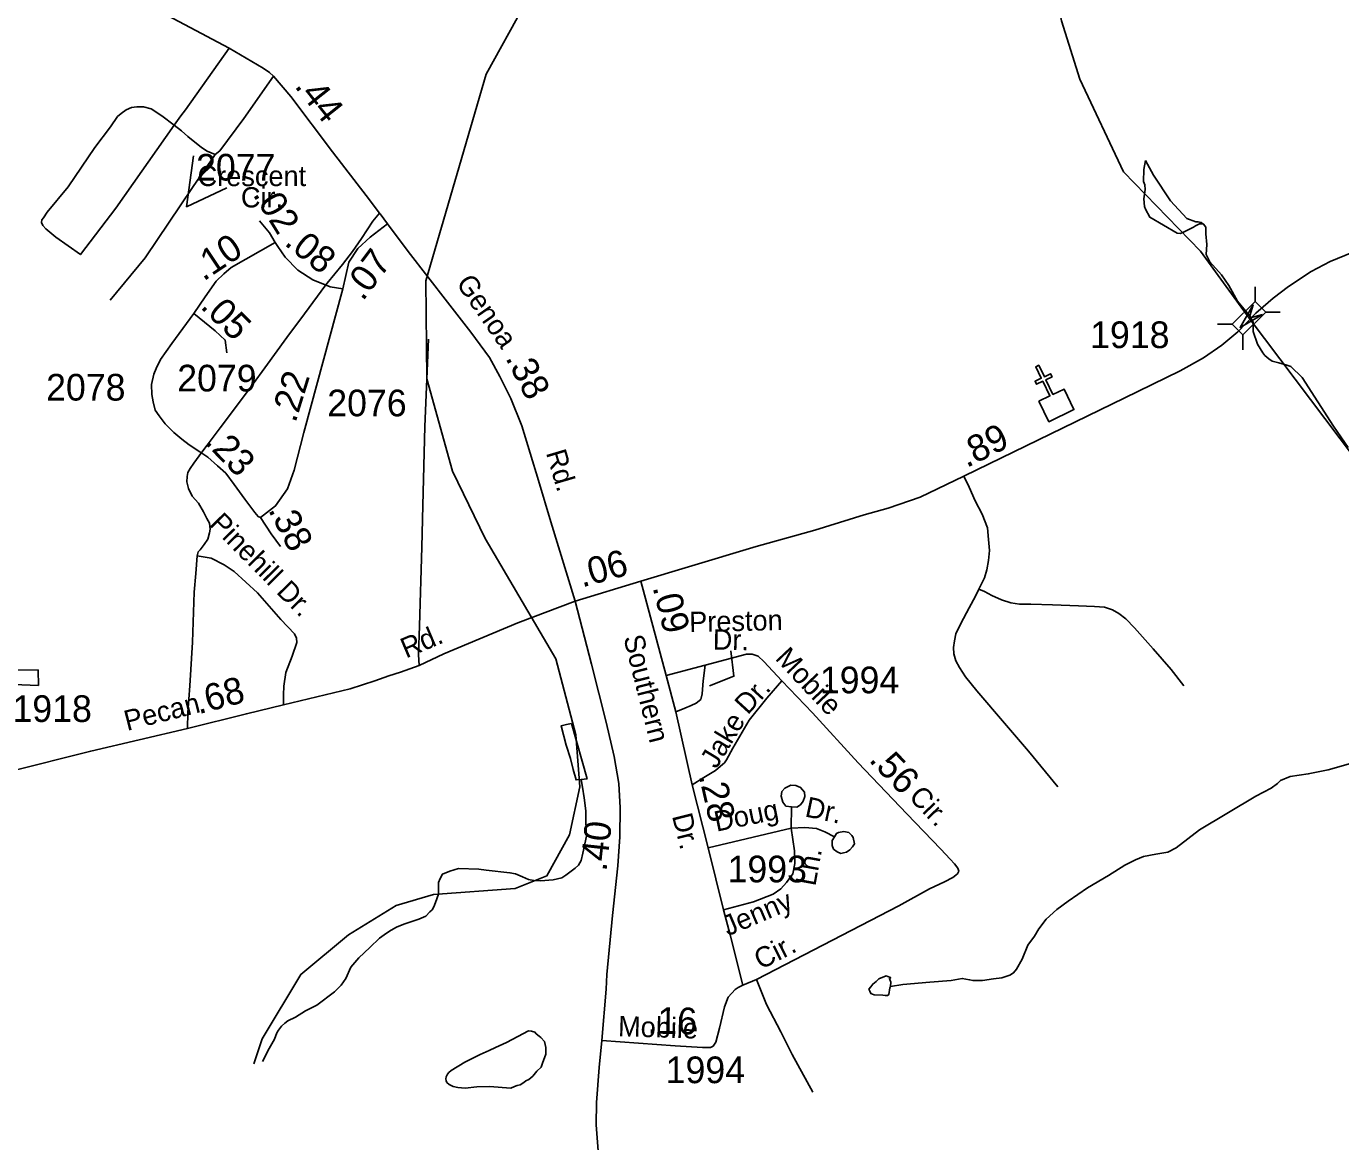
# Model space of a CAD drawing. Extents: x 2206922 to 2357709, y 510027 to 673830.
# Drawn here: x 2290689 to 2296847, y 569227 to 574452 of the extents above; entities that cross this region are included whole.
import ezdxf

# ---------------------------------------------------------------- set-up
doc = ezdxf.new("R2010")
doc.units = 0
for name, color, linetype in [('Exist Cultural Church CELL', 7, 'Continuous'), ('Exist Hydrographic Creek Single Shore', 7, 'Continuous'), ('Exist Hydrographic Misc Water Feature', 7, 'Continuous'), ('Exist Road Non-System Type 51', 7, 'Continuous'), ('Exist Road Non-System Type 51 Label', 7, 'Continuous'), ('Exist Road Secondary Mileage Hundredths English Label', 7, 'Continuous'), ('Exist Road Secondary Structure Standard Bridge Attributed CELL', 7, 'Continuous'), ('Exist Road Secondary Structure Standard Bridge CELL', 7, 'Continuous'), ('Exist Road Secondary Type 51 Attributed', 7, 'Continuous'), ('Exist Road Secondary Type 51 Label', 7, 'Continuous'), ('Exist Road Secondary Type 51 Number Label', 7, 'Continuous')]:
    doc.layers.add(name, color=color, linetype=linetype)

msp = doc.modelspace()

# ---------------------------------------------------------------- linework, layer by layer
at = {"layer": 'Exist Cultural Church CELL'}
msp.add_lwpolyline([(2295432.8, 572695.4), (2295484, 572720.3), (2295450.9, 572788.8), (2295422.1, 572774.9), (2295415.1, 572789.3), (2295443.9, 572803.2), (2295417.7, 572857.3), (2295432.2, 572864.3), (2295458.4, 572810.2), (2295487.2, 572824.1), (2295494.1, 572809.7), (2295465.3, 572795.8), (2295498.5, 572727.3), (2295550.4, 572752.3), (2295596.8, 572656.4), (2295479.2, 572599.6)], close=True, dxfattribs=at)
at = {"layer": 'Exist Hydrographic Creek Single Shore'}
msp.add_lwpolyline([(2298399.1, 570596.1), (2298213.1, 570829.4), (2297917, 571350.3), (2297059.1, 572233.4), (2296418, 573084.2), (2296190, 573398.7), (2295828.9, 573770.1), (2295624.9, 574203.8), (2295539, 574477.8), (2295494.9, 574701.6), (2295534.9, 574851.6), (2295857.9, 575114.1), (2295931.9, 575247), (2295937, 575505.9), (2295807, 576118.6), (2295793.9, 576561.6), (2295972.9, 577053.2)], dxfattribs=at)
at = {"layer": 'Exist Hydrographic Misc Water Feature'}
for points in [[(2291753.9, 569592.4), (2291793.9, 569709.7), (2291975, 570011), (2292197.9, 570196.7), (2292421, 570333.2), (2292595.9, 570385.4), (2292978.9, 570413.8), (2293128, 570473.1), (2293234, 570664.4), (2293282, 570889.7), (2293262.9, 571132.8), (2293169, 571488.9), (2292837.9, 572053), (2292685.9, 572367.7), (2292564.9, 572799.7), (2292560.8, 573259), (2292843, 574227.2), (2293023, 574551.6), (2293477, 575031), (2293858, 575200.4), (2294113.9, 575411.7), (2295024.9, 576836.2), (2295100, 576897.1), (2295972.9, 577053.2)], [(2296200.3, 573526.1), (2296184.5, 573526), (2296166.1, 573517.8), (2296156.6, 573511.6), (2296106.8, 573485.4), (2296094.5, 573481.2), (2296080.8, 573482.8), (2295952.2, 573557.7), (2295931.7, 573595.3), (2295927.2, 573607.3), (2295923.5, 573643.2), (2295930.9, 573687.5), (2295929, 573709.3), (2295922.2, 573725.3), (2295923.9, 573781.4), (2295931.3, 573823.2)], [(2296200.3, 573526.1), (2296192.3, 573532.1), (2296177.9, 573535.9), (2296168.3, 573535.8), (2296126.3, 573551.4), (2296049.2, 573634.4), (2295970.2, 573753.7), (2295931.3, 573823.2)], [(2296881.5, 572479), (2296812.6, 572578.2), (2296666.6, 572807), (2296612.2, 572858.2), (2296594.2, 572864.2), (2296556.1, 572875.5), (2296525.9, 572883.3), (2296509.7, 572893.5), (2296491.5, 572909.2), (2296481.4, 572922.9), (2296457, 572962.6), (2296436.9, 573022.5), (2296436.7, 573064.6), (2296424.4, 573090.4), (2296363.5, 573163.7), (2296322.7, 573237.6), (2296288.3, 573286.9), (2296233.5, 573348.3), (2296215.5, 573382.3), (2296219.2, 573430.4), (2296214.6, 573480.1), (2296214, 573510.2), (2296204.2, 573524.3), (2296200.3, 573526.1)], [(2290745.5, 571364.1), (2290744.7, 571436.1), (2290613, 571436.8), (2290548.9, 571434.3), (2290539, 571426.1), (2290531.4, 571417.9), (2290531.6, 571404.1), (2290537.8, 571390.2), (2290537.6, 571384.1), (2290541.5, 571382.3), (2290547.4, 571372.1), (2290745.5, 571364.1)], [(2293219.9, 571181.3), (2293194, 571175), (2293218.6, 571085.3), (2293237.5, 571021.7), (2293250, 570969.9), (2293264.2, 570922), (2293288.4, 570924)], [(2293288.4, 570924), (2293316.2, 570926.3), (2293242.2, 571185.6), (2293219.9, 571181.3)], [(2294736.6, 569954.5), (2294794.5, 569962.8), (2294922.2, 569974), (2295022.3, 569982.8), (2295073.7, 569991.7), (2295108.2, 569985.7), (2295124.2, 569982.1), (2295168.3, 569982.3), (2295219.9, 569990.8), (2295259.7, 569995.3), (2295277.8, 570001.5), (2295295.8, 570007.7), (2295313.7, 570017.6), (2295327.2, 570035.8), (2295354.9, 570082), (2295380.5, 570148.3), (2295411.7, 570190.6), (2295431.8, 570224.5), (2295467.2, 570269), (2295516.7, 570315.5), (2295570.2, 570354.1), (2295659.8, 570416.9), (2295759.2, 570473.6), (2295834.5, 570522.3), (2295884.5, 570546.8), (2295922, 570563.1), (2295980.1, 570573.8), (2296036, 570584), (2296075.6, 570604.4), (2296185.1, 570687.7), (2296449, 570845.8), (2296520.6, 570882.5), (2296550.5, 570904.7), (2296564.5, 570918.9), (2296610, 570937.5), (2296694.3, 570950), (2296788, 570969.2), (2296891.7, 570998.1)], [(2291795.6, 569603), (2291826.7, 569663.2), (2291850.7, 569707.4), (2291862.4, 569737.3), (2291870, 569749.5), (2291884.2, 569767.7), (2291900.1, 569781.9), (2291913.5, 569794.1), (2291949.8, 569810.1), (2291996.9, 569840.7), (2292049, 569867), (2292132.5, 569929.8), (2292164.1, 569960.3), (2292185.4, 569992.4), (2292209, 570044.4), (2292246.5, 570089), (2292298.4, 570137.2), (2292343.7, 570179.8), (2292375.9, 570204.2), (2292397.4, 570218.4), (2292423.4, 570232.3), (2292457.3, 570246.7), (2292527, 570269.4), (2292560.8, 570283.8), (2292578.7, 570303.8), (2292590.4, 570313.8), (2292598.4, 570328), (2292606.3, 570347.9), (2292619.5, 570386.1), (2292619.3, 570426.2), (2292619.5, 570442), (2292627.3, 570460.3), (2292639, 570480.4), (2292672.4, 570494.5), (2292712.8, 570507), (2292808.7, 570504), (2292842.6, 570498.4), (2292954.7, 570487.2), (2292981, 570481.7), (2293012.8, 570468), (2293040.9, 570456), (2293066.7, 570450.5), (2293097, 570448.7), (2293156.9, 570453.2), (2293196.9, 570463.7), (2293216.8, 570475.8), (2293260.3, 570508.1), (2293276.3, 570522.3), (2293288.1, 570544.5), (2293295.9, 570578.6), (2293313, 570658.7), (2293310.3, 570726.4), (2293309.7, 570776.4), (2293302.9, 570838.3), (2293294.7, 570888.2), (2293288.4, 570924)], [(2294736.6, 569954.5), (2294738.7, 569974.5), (2294734.2, 569986.5), (2294732.1, 569992), (2294738.5, 569996.3), (2294731.9, 569998.1), (2294716.3, 570004.1), (2294682.5, 569989.8), (2294670.4, 569977.8), (2294654.2, 569965.6), (2294644.6, 569953.3), (2294636.6, 569941.5), (2294640.9, 569931.6), (2294644.8, 569921.7), (2294660.8, 569915.6), (2294701, 569914), (2294712.8, 569912.2), (2294722.7, 569912.4), (2294728.8, 569916.3), (2294734.6, 569948.3), (2294736.6, 569954.5)], [(2292814.7, 569636.4), (2292743.1, 569599.8), (2292679.3, 569561.1), (2292667.5, 569551.1), (2292661.5, 569543.1), (2292655.8, 569531), (2292654.1, 569521.1), (2292656.2, 569513.1), (2292658.2, 569505.1), (2292670.1, 569495.2), (2292688, 569485.2), (2292709.9, 569481.5), (2292744.1, 569478), (2292800.1, 569484.5), (2292857.9, 569485.2), (2292958.4, 569477.8), (2292975.9, 569486.1), (2292988.2, 569490.3), (2293001.9, 569494.3), (2293019.7, 569504.6), (2293029.6, 569512.4), (2293043.7, 569518.8), (2293061.4, 569534.8), (2293081.2, 569557), (2293101.1, 569577.1), (2293106.7, 569595.3), (2293122.7, 569637.5), (2293122.5, 569669.2), (2293116.1, 569697.3), (2293099.9, 569715.2), (2293091.5, 569720.9), (2293077.8, 569733.1), (2293071.4, 569740.9), (2293055.4, 569744.5), (2293041.3, 569746.7), (2292991.8, 569720), (2292938.3, 569691.6), (2292886.4, 569669), (2292856.5, 569654.9), (2292814.7, 569636.4)]]:
    msp.add_lwpolyline(points, dxfattribs=at)
at = {"layer": 'Exist Road Non-System Type 51'}
for p, q in [((2294272.2, 570695.5), (2294273.2, 570795.4)), ((2293883.7, 570604.2), (2294272.2, 570695.5))]:
    msp.add_line(p, q, dxfattribs=at)
for points in [[(2291638.5, 574348.7), (2291434, 574061), (2291412.2, 574031.8), (2291381.1, 573988.7)], [(2291573.9, 573850.5), (2291595.8, 573868.6), (2291707, 574019.3), (2291846.6, 574218.2)], [(2291381.1, 573988.7), (2291323.9, 574032.6), (2291273.1, 574064.8), (2291237.1, 574073.8), (2291207.1, 574073.8), (2291181.6, 574070.8), (2291156.1, 574060.3), (2291133.6, 574043.7), (2291115.6, 574028.7), (2291082.6, 573980.7), (2291009.1, 573884.7), (2290884.6, 573700.1), (2290787.1, 573581.5), (2290768.4, 573555.2), (2290760.9, 573544.7), (2290759.4, 573532.7), (2290765.4, 573519.2), (2290780.4, 573502.7), (2290826.8, 573463.7), (2290942.3, 573382.7), (2291107.3, 573600.3), (2291381.1, 573988.7)], [(2291381.1, 573988.7), (2291415.7, 573962.1), (2291445, 573935.4), (2291510.1, 573883.5), (2291536.7, 573866.2), (2291573.9, 573850.5)], [(2291081.8, 573169.5), (2291245.3, 573367.6), (2291467.3, 573696.3), (2291573.9, 573850.5)], [(2292343.3, 573577.1), (2292311.7, 573538.7), (2292258.8, 573458.5), (2292217.3, 573397), (2292170.1, 573335.4), (2292098.5, 573248), (2292092.5, 573240.1)], [(2292092.5, 573240.1), (2291991.2, 573104.9), (2291909.6, 572994.6), (2291806.2, 572851.5)], [(2292572.9, 572986.7), (2292555.7, 572577.2), (2292547.1, 572207.8), (2292541.4, 572011.7), (2292531.4, 571643.7), (2292526.4, 571509.8), (2292529.2, 571458.3)], [(2291806.2, 572851.5), (2291793.7, 572834.3), (2291735, 572754.1), (2291596.2, 572570.8), (2291535.9, 572490.3)], [(2291535.9, 572490.3), (2291510.4, 572456.3), (2291473.2, 572404.7), (2291456, 572380.4), (2291446, 572361.8), (2291441.7, 572343.1), (2291440.2, 572317.4), (2291448.8, 572287.3), (2291466, 572251.5), (2291494.6, 572218.6), (2291519, 572177.1), (2291534.7, 572147), (2291547.6, 572124.1), (2291550.4, 572096.9), (2291547.6, 572079.7), (2291539, 572049.6), (2291521.8, 572023.9), (2291503.2, 571999.5), (2291493.2, 571989.5), (2291488.9, 571970.9)], [(2295150.5, 571815.2), (2295177.3, 571867.8), (2295188, 571906.4), (2295196.6, 571949.4), (2295200.9, 571996.6), (2295196.6, 572048.2), (2295192.3, 572101.9), (2295166.6, 572166.3), (2295134.4, 572228.6), (2295106.5, 572293), (2295080.7, 572344.6)], [(2291488.9, 571970.9), (2291483.2, 571889.3), (2291474.6, 571800.5), (2291467.4, 571567.1), (2291454.6, 571362.4), (2291446, 571237.8), (2291444.5, 571163.3)], [(2291893.2, 571272.9), (2291893.2, 571320.1), (2291894.6, 571361.6), (2291904.6, 571424.6), (2291934.7, 571502), (2291956.1, 571565), (2291954.7, 571586.4), (2291945.4, 571605.8), (2291881, 571673.1), (2291772.2, 571797.6), (2291662.1, 571897.9), (2291616.3, 571929.4), (2291554.7, 571960.9), (2291488.9, 571970.9)], [(2295521.8, 570889.5), (2295384.4, 571057), (2295270.7, 571188), (2295141.9, 571338.4), (2295088.2, 571405), (2295060.3, 571447.9), (2295043.1, 571480.1), (2295034.6, 571512.3), (2295032.4, 571542.4), (2295036.7, 571572.5), (2295043.1, 571606.8), (2295066.8, 571654.1), (2295105.4, 571727.1), (2295135.4, 571782.9), (2295150.5, 571815.2)], [(2296112.1, 571362), (2296052, 571439.3), (2295968.3, 571536), (2295880.3, 571634.8), (2295840.6, 571676.6), (2295807.3, 571701.3), (2295777.2, 571718.5), (2295739.7, 571730.3), (2295693.5, 571733.6), (2295618.4, 571737.8), (2295496.1, 571742.1), (2295395.2, 571744.3), (2295341.5, 571744.3), (2295300.7, 571750.7), (2295257.8, 571765.8), (2295212.7, 571785.1), (2295178.4, 571804.4), (2295150.5, 571815.2)], [(2293731.2, 571240.2), (2293773.2, 571258.6), (2293803, 571270.8), (2293826.8, 571281.1), (2293848.6, 571299.2), (2293854.5, 571325.3), (2293859.9, 571385.4), (2293868.4, 571458.8)], [(2293808.6, 570899), (2293862.2, 570933.5), (2293917.8, 570966), (2293941.6, 570986.3), (2293959.3, 571002.5), (2293969.2, 571016.5), (2293998.7, 571070.7), (2294075.5, 571201.5), (2294158.4, 571304.2), (2294228.2, 571385.4)], [(2294273.2, 570795.4), (2294247.1, 570799.2), (2294233.1, 570817.1), (2294224.7, 570845), (2294228.5, 570867.1), (2294242.4, 570883.2), (2294270.3, 570897.5), (2294294.2, 570895.6), (2294316.2, 570885.9), (2294334.6, 570864), (2294336.6, 570844.1), (2294328.9, 570821.9), (2294315, 570805.8), (2294299.2, 570793.7), (2294273.2, 570795.4)], [(2293955.2, 570313.6), (2294095.5, 570350.8), (2294187.1, 570386.6), (2294222.8, 570410.9), (2294250, 570441), (2294280.1, 570482.5), (2294288.7, 570529.8), (2294287.2, 570589.9), (2294272.2, 570695.5)], [(2294272.2, 570695.5), (2294336, 570698.2), (2294390.2, 570694.7), (2294430.2, 570679.1), (2294474.3, 570655.4)], [(2294474.3, 570655.4), (2294464.6, 570637.4), (2294464.7, 570615.4), (2294471, 570597.5), (2294487.1, 570585.6), (2294505.1, 570577.8), (2294517, 570580), (2294531.1, 570584.1), (2294546.9, 570594.2), (2294558.7, 570608.3), (2294568.6, 570622.3), (2294562.4, 570652.3), (2294556.2, 570662.2), (2294542.1, 570676.1), (2294518.2, 570679.9), (2294494.1, 570675.6), (2294484.2, 570671.6), (2294474.3, 570655.4)], [(2294373.5, 569458.7), (2294276.3, 569635.7), (2294223.2, 569741.2), (2294156.3, 569869.8), (2294109.1, 569986.4)]]:
    msp.add_lwpolyline(points, dxfattribs=at)
at = {"layer": 'Exist Road Non-System Type 51 Label'}
for points in [[(2291628, 573695.6), (2291439.2, 573606.7), (2291472.5, 573845.6)], [(2293989.7, 571527.2), (2294003.6, 571407.7), (2293889.7, 571363.2)]]:
    msp.add_lwpolyline(points, dxfattribs=at)
at = {"layer": 'Exist Road Secondary Structure Standard Bridge Attributed CELL'}
msp.add_lwpolyline([(2296480.4, 573102.2), (2296375, 573041), (2296435.7, 573146.7), (2296418, 573084.2)], close=True, dxfattribs=at)
at = {"layer": 'Exist Road Secondary Structure Standard Bridge CELL'}
for p, q in [((2296446, 573162.2), (2296446.4, 573231.1)), ((2296494.5, 573113.1), (2296563.5, 573112.6)), ((2296269.3, 573056.6), (2296338.3, 573056.2)), ((2296387.4, 572937), (2296387.9, 573006))]:
    msp.add_line(p, q, dxfattribs=at)
msp.add_lwpolyline([(2296338.3, 573056.2), (2296445.8, 573162.4), (2296495.4, 573112.2), (2296387.9, 573006)], close=True, dxfattribs=at)
at = {"layer": 'Exist Road Secondary Type 51 Attributed'}
for q in [(2293260.7, 571759.8), (2293686.4, 571411.3)]:
    msp.add_line((2293567.7, 571852.3), q, dxfattribs=at)
for points in [[(2292381.1, 573526.4), (2292346.8, 573572.6), (2292343.3, 573577.1), (2292280.6, 573659.1), (2292122.8, 573864.2), (2291928.1, 574122.7), (2291846.6, 574218.2), (2291827.5, 574236), (2291798.2, 574256.4), (2291638.5, 574348.7), (2291219.8, 574571.5), (2290924.8, 574722.4), (2290559.5, 574909.1)], [(2297791, 573779.2), (2297673, 573724.1), (2297406.8, 573605.3), (2296976.8, 573422.7), (2296796.5, 573349.7), (2296707.8, 573302.5), (2296601.9, 573233.7), (2296530.3, 573177.9), (2296448.7, 573107.7), (2296402.2, 573060)], [(2291855, 573439.2), (2291827.5, 573484.7), (2291781.6, 573539.8)], [(2292381.1, 573526.4), (2292299.1, 573464.2), (2292242.3, 573410.2), (2292199.7, 573347.7), (2292171.3, 573222.7)], [(2293260.7, 571759.8), (2293146, 572130), (2293087.6, 572324.3), (2293010.2, 572579.7), (2292958.6, 572708.8), (2292907, 572810.7), (2292858.1, 572900.4), (2292771.2, 573018.6), (2292662.5, 573159.9), (2292477.9, 573396.3), (2292381.1, 573526.4)], [(2291855, 573439.2), (2291648.5, 573322.1), (2291614.1, 573292.3), (2291577.4, 573257.9), (2291526.9, 573184.4), (2291474.1, 573106.3)], [(2292171.3, 573222.7), (2292112.1, 573232.1), (2292031.7, 573264.3), (2291960.6, 573310.2), (2291900.9, 573369.9), (2291866.5, 573420.4), (2291855, 573439.2)], [(2292171.3, 573222.7), (2291989.5, 572549.4), (2291944.1, 572373.2), (2291912.9, 572285.2), (2291856.1, 572205.6), (2291785.1, 572151.6)], [(2291474.1, 573106.3), (2291370.8, 572966.3), (2291318, 572890.5), (2291297.4, 572849.2), (2291285.9, 572821.6), (2291274.4, 572773.4), (2291276.7, 572727.5), (2291283.6, 572693.1), (2291292.8, 572654), (2291311.2, 572626.5), (2291338.7, 572589.7), (2291380, 572548.4), (2291416.7, 572518.6), (2291451.1, 572491), (2291501.6, 572458.9), (2291538.4, 572433.6), (2291584.2, 572392.3), (2291623.3, 572357.9), (2291662.3, 572305.1), (2291712.8, 572236.2), (2291758.7, 572174.2), (2291774.7, 572155.8), (2291785.1, 572151.6)], [(2291474.1, 573106.3), (2291572.8, 573026), (2291621, 572982.3), (2291627.9, 572922.7)], [(2296402.2, 573060), (2296364.3, 573021.1), (2296289.2, 572958.8), (2296203.3, 572898.7), (2296093.9, 572838.5), (2295832, 572709.7), (2295430.6, 572514.2), (2295080.7, 572344.6), (2294875.7, 572246.9), (2294725.7, 572195), (2294614.2, 572164), (2294383, 572091.7), (2294107.8, 572015.3), (2293791, 571920.4), (2293567.7, 571852.3)], [(2291785.1, 572151.6), (2291836.2, 572074.9), (2291878.8, 572015.3)], [(2293260.7, 571759.8), (2292991.8, 571657), (2292645.4, 571511.9), (2292529.2, 571458.3), (2292442.3, 571426), (2292386.4, 571409.4), (2292321, 571386), (2292206.5, 571348.8), (2291893.2, 571272.9), (2291720, 571231.4), (2291444.5, 571163.3), (2290990.6, 571056.6), (2290605.6, 570959), (2290316.6, 570882.3), (2290047.4, 570817.7), (2289826.5, 570767)], [(2293384.8, 569701.1), (2293404.6, 569941.2), (2293408.6, 570010), (2293435.1, 570287.1), (2293459.4, 570519), (2293468.7, 570655.8), (2293470.1, 570790.4), (2293464.4, 570904.9), (2293442, 571030.8), (2293406, 571191.8), (2293337, 571464.7), (2293260.7, 571759.8)], [(2294585.1, 571002.3), (2294371.3, 571235.9), (2294228.2, 571385.4), (2294144.2, 571476.1), (2294116.9, 571500.9), (2294089, 571511.3), (2294062.6, 571510.4), (2293868.4, 571458.8), (2293686.4, 571411.3)], [(2293686.4, 571411.3), (2293731.2, 571240.2), (2293808.6, 570899), (2293883.7, 570604.2), (2293955.2, 570313.6), (2293986.2, 570195.7), (2294045.5, 569960.9)], [(2294045.5, 569960.9), (2294109.1, 569986.4), (2294776.6, 570332.2), (2294919.7, 570412.4), (2294989.8, 570443.9), (2295029.9, 570465.3), (2295051.4, 570482.5), (2295057.1, 570494), (2295052.8, 570508.3), (2295037.3, 570528.9), (2295017, 570551.3), (2294972.7, 570597.1), (2294813.9, 570763.4), (2294585.1, 571002.3)], [(2293384.8, 569701.1), (2293728.1, 569676.8), (2293857.2, 569667.7), (2293893.6, 569667.7), (2293905.8, 569675.3), (2293919.4, 569693.5), (2293936.1, 569758.8), (2293960.4, 569859.1), (2293977.1, 569904.7), (2294009, 569940.4), (2294024.2, 569949.5), (2294045.5, 569960.9)], [(2294321.9, 565778.3), (2294285.4, 565872.5), (2294247.5, 565997.1), (2294188.2, 566182.5), (2294101.7, 566443.9), (2293996.9, 566768.3), (2293903, 567057.4), (2293875.7, 567141.5), (2293815.5, 567348.9), (2293782.7, 567474.9), (2293649.1, 568001.4), (2293541.3, 568419.3), (2293460.8, 568723.2), (2293436.5, 568822), (2293393.9, 568995.2), (2293371.2, 569143.4), (2293359, 569306), (2293360.5, 569411.6), (2293372.7, 569575), (2293384.8, 569701.1)]]:
    msp.add_lwpolyline(points, dxfattribs=at)

# ---------------------------------------------------------------- texts
at = {"layer": 'Exist Road Non-System Type 51 Label'}
for s, p in [('Crescent', (2291491.3, 573703.2)), ('Cir.', (2291694.2, 573603.2))]:
    msp.add_text(s, height=95, dxfattribs=at).set_placement(p)
for s, rotation, p in [('Pinehill', 314.7155, (2291542.2, 572116.2)), ('Dr.', 314.7155, (2291856.2, 571799.1)), ('Preston', 1.28317, (2293795.3, 571614.1)), ('Dr.', 358.82276, (2293904, 571532.6)), ('Dr.', 47.5652, (2294068.3, 571223.3)), ('Jake', 58.75799, (2293921.1, 570969.8)), ('Doug', 11.44807, (2293921.8, 570679.1)), ('Dr.', 348.07256, (2294332.4, 570751.3)), ('Ln.', 79.68303, (2294385, 570421.1)), ('Jenny', 22.97206, (2293975.4, 570188.8))]:
    msp.add_text(s, height=95, rotation=rotation, dxfattribs=at).set_placement(p)
at = {"layer": 'Exist Road Secondary Mileage Hundredths English Label'}
for s, rotation, p in [('.44', 308.48837, (2291942, 574170.5)), ('.02', 301.93691, (2291746.9, 573664.8)), ('.10', 33.75521, (2291518.6, 573255.2)), ('.08', 321.13576, (2291892.8, 573430.8)), ('.07', 53.03963, (2292265, 573160.8)), ('.05', 315.10119, (2291500, 573135.8)), ('.38', 297.17327, (2292931.1, 572898.8)), ('.22', 72.73498, (2291949.5, 572590.8)), ('.89', 26.40016, (2295093.8, 572381.9)), ('.23', 314.10078, (2291520.2, 572501)), ('.38', 297.17327, (2291820.2, 572187.4)), ('.06', 15.37585, (2293292.4, 571822.8)), ('.09', 284.09179, (2293622.1, 571824.2)), ('.68', 14.87711, (2291495.9, 571228.9)), ('.56', 313.9934, (2294631.9, 571012.6)), ('.28', 282.89276, (2293838.6, 570942.5)), ('.40', 83.71736, (2293406.5, 570490.8)), ('.16', 358.93978, (2293598.3, 569733.8))]:
    msp.add_text(s, height=125, rotation=rotation, dxfattribs=at).set_placement(p)
at = {"layer": 'Exist Road Secondary Type 51 Label'}
for s, rotation, p in [('Genoa', 304.67592, (2292699.5, 573248.3)), ('Rd.', 286.4538, (2293122.5, 572454.2)), ('Rd.', 22.92537, (2292467.5, 571490)), ('Southern', 284.09179, (2293485.5, 571589.1)), ('Mobile', 313.32174, (2294192.6, 571488.1)), ('Pecan', 14.3471, (2291160.7, 571150.9)), ('Cir.', 313.69059, (2294818.7, 570838.9)), ('Dr.', 284.21534, (2293713.2, 570753.1)), ('Cir.', 27.09655, (2294129.2, 570031.2)), ('Mobile', 358.23891, (2293460, 569721.4))]:
    msp.add_text(s, height=95, rotation=rotation, dxfattribs=at).set_placement(p)
at = {"layer": 'Exist Road Secondary Type 51 Number Label'}
for s, p in [('2077', (2291483.9, 573729.1)), ('1918', (2295672.5, 572944.5)), ('2078', (2290781.4, 572698.6)), ('2079', (2291395.7, 572741.3)), ('2076', (2292098.6, 572624.9)), ('1994', (2294406.5, 571327.5)), ('1918', (2290623.8, 571193.2)), ('1993', (2293974.1, 570442)), ('1994', (2293684.1, 569501.4))]:
    msp.add_text(s, height=125, dxfattribs=at).set_placement(p)

doc.saveas('drawing.dxf')
